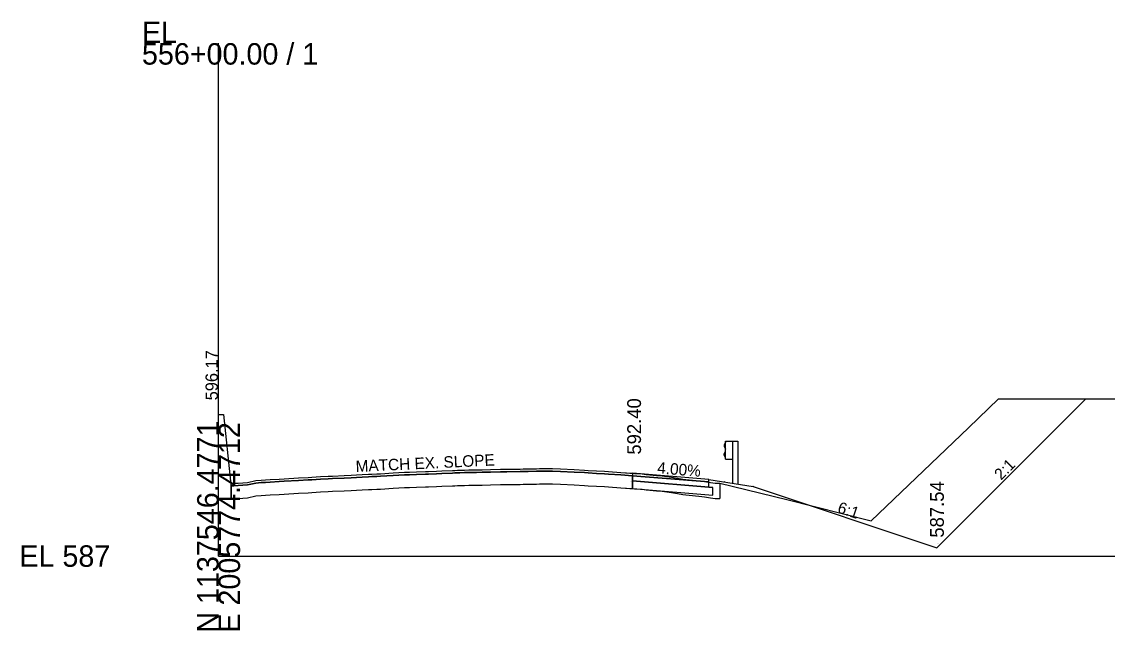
# Model space of a CAD drawing. Extents: x -201 to 2007062, y -213 to 1139737.
# Drawn here: x -25.7 to 116, y 8990.3 to 9069.8 of the extents above; entities that cross this region are included whole.
import ezdxf

# ---------------------------------------------------------------- set-up
doc = ezdxf.new("R2010")
doc.units = 0
for name, color, linetype in [('Default', 7, 'Continuous'), ('RD_GPK_XS_Cell', 7, 'Continuous'), ('RD_Sketch1', 7, 'Continuous'), ('RD_XS_Base', 7, 'Continuous'), ('RD_XS_ExGround', 7, 'Continuous'), ('RD_XS_ExPaveRet', 7, 'Continuous'), ('RD_XS_GR', 7, 'Continuous'), ('RD_XS_PaveOvlay', 7, 'Continuous'), ('RD_XS_PaveShd', 7, 'Continuous'), ('RD_XS_TieSlope', 7, 'Continuous'), ('RD_XS_TX_Ditch', 7, 'Continuous'), ('RD_XS_TX_Elev_EX', 7, 'Continuous'), ('RD_XS_TX_Elev_PR', 7, 'Continuous'), ('RD_XS_TX_Slope', 7, 'Continuous')]:
    doc.layers.add(name, color=color, linetype=linetype)

msp = doc.modelspace()

# ---------------------------------------------------------------- linework, layer by layer
at = {"layer": 'RD_GPK_XS_Cell'}
for q in [(0, 9066.96), (250, 9000)]:
    msp.add_line((0, 9000), q, dxfattribs=at)
at = {"layer": 'RD_XS_Base'}
for points in [[(64, 9009.67), (54, 9010.47)], [(54, 9010.47), (54, 9009.81)], [(64.5, 9008.97), (54, 9009.81)], [(54, 9009.81), (54, 9008.81)], [(54, 9009.81), (64.5, 9008.97)], [(64, 9009.01), (64, 9009.67)], [(54, 9008.81), (64.5, 9007.97)], [(64.5, 9007.97), (64.5, 9008.97)]]:
    msp.add_lwpolyline(points, dxfattribs=at)
at = {"layer": 'RD_XS_ExGround'}
msp.add_lwpolyline([(0, 9018.33), (0.02, 9018.49), (0.62, 9018.48), (1.54, 9009.76), (1.64, 9009.48), (1.99, 9009.5), (2.56, 9009.53), (3.79, 9009.61), (4.87, 9009.86), (5.55, 9009.92), (6.14, 9009.95), (6.74, 9009.99), (7.92, 9010.05), (8.58, 9010.09), (10.43, 9010.2), (11.71, 9010.27), (12.17, 9010.3), (13.28, 9010.37), (14.29, 9010.43), (14.85, 9010.45), (16.41, 9010.52), (17.31, 9010.56), (17.98, 9010.6), (18.72, 9010.66), (19.55, 9010.69), (20.02, 9010.71), (20.65, 9010.73), (21.12, 9010.75), (22.78, 9010.86), (24.25, 9010.93), (24.9, 9010.96), (25.82, 9010.99), (27.02, 9011.03), (27.38, 9011.04), (28.42, 9011.09), (29.14, 9011.12), (30.52, 9011.17), (30.83, 9011.18), (31.18, 9011.2), (31.49, 9011.21), (32.08, 9011.22), (32.64, 9011.24), (33.65, 9011.24), (34.41, 9011.26), (35.5, 9011.29), (36.79, 9011.33), (37.63, 9011.34), (39.38, 9011.36), (39.75, 9011.37), (40.41, 9011.38), (41.49, 9011.4), (41.87, 9011.41), (42.55, 9011.43), (42.98, 9011.43), (43.57, 9011.41), (44.62, 9011.39), (46.41, 9011.29), (47.76, 9011.22), (48.23, 9011.18), (49.32, 9011.11), (50.35, 9011.07), (50.89, 9011.04), (52.48, 9010.92), (54.27, 9010.78), (54.58, 9010.76), (55.3, 9010.72), (55.8, 9010.66), (56.72, 9010.56), (57.16, 9010.52), (57.87, 9010.46), (59.1, 9010.28), (59.9, 9010.16), (60.58, 9010.04), (60.96, 9010), (61.86, 9009.91), (63.08, 9009.78), (63.43, 9009.72), (64.18, 9009.59), (64.49, 9009.55), (64.79, 9009.5), (65.43, 9009.52), (74.18, 9007.39), (85.17, 9004.59), (97.87, 9016.76), (101.8, 9020.52), (113.57, 9020.53), (120.72, 9020.53)], dxfattribs=at)
at = {"layer": 'RD_XS_ExPaveRet'}
for p, q in [((1.64, 9007.48), (1.64, 9009.48)), ((1.64, 9009.15), (1.64, 9007.48)), ((27.38, 9009.04), (28.42, 9009.09)), ((27.38, 9009.04), (28.42, 9009.09)), ((28.42, 9009.09), (29.14, 9009.12)), ((28.42, 9009.09), (29.14, 9009.12)), ((29.14, 9009.12), (30.52, 9009.17)), ((29.14, 9009.12), (30.52, 9009.17)), ((30.52, 9009.17), (30.83, 9009.18)), ((30.52, 9009.17), (30.83, 9009.18)), ((30.83, 9009.18), (31.18, 9009.2)), ((30.83, 9009.18), (31.18, 9009.2)), ((31.18, 9009.2), (31.49, 9009.21)), ((31.18, 9009.2), (31.49, 9009.21)), ((31.49, 9009.21), (32.08, 9009.22)), ((31.49, 9009.21), (32.08, 9009.22)), ((32.08, 9009.22), (32.64, 9009.24)), ((32.08, 9009.22), (32.64, 9009.24)), ((32.64, 9009.24), (33.65, 9009.24)), ((32.64, 9009.24), (33.65, 9009.24)), ((33.65, 9009.24), (34.41, 9009.26)), ((33.65, 9009.24), (34.41, 9009.26)), ((34.41, 9009.26), (35.5, 9009.29)), ((34.41, 9009.26), (35.5, 9009.29)), ((35.5, 9009.29), (36.79, 9009.33)), ((35.5, 9009.29), (36.79, 9009.33)), ((36.79, 9009.33), (37.63, 9009.34)), ((36.79, 9009.33), (37.63, 9009.34)), ((37.63, 9009.34), (39.38, 9009.36)), ((37.63, 9009.34), (39.38, 9009.36)), ((39.38, 9009.36), (39.75, 9009.37)), ((39.38, 9009.36), (39.75, 9009.37)), ((39.75, 9009.37), (40.41, 9009.38)), ((39.75, 9009.37), (40.41, 9009.38)), ((40.41, 9009.38), (41.49, 9009.4)), ((40.41, 9009.38), (41.49, 9009.4)), ((41.49, 9009.4), (41.87, 9009.41)), ((41.49, 9009.4), (41.87, 9009.41)), ((41.87, 9009.41), (42.55, 9009.43)), ((41.87, 9009.41), (42.55, 9009.43)), ((42.55, 9009.43), (42.98, 9009.43)), ((42.55, 9009.43), (42.98, 9009.43)), ((42.98, 9009.43), (43.57, 9009.41)), ((42.98, 9009.43), (43.57, 9009.41)), ((43.57, 9009.41), (44.62, 9009.39)), ((43.57, 9009.41), (44.62, 9009.39)), ((44.62, 9009.39), (46.41, 9009.29)), ((44.62, 9009.39), (46.41, 9009.29)), ((46.41, 9009.29), (47.76, 9009.22)), ((46.41, 9009.29), (47.76, 9009.22)), ((47.76, 9009.22), (48.23, 9009.18)), ((47.76, 9009.22), (48.23, 9009.18)), ((48.23, 9009.18), (49.32, 9009.11)), ((48.23, 9009.18), (49.32, 9009.11)), ((49.32, 9009.11), (50.35, 9009.07)), ((49.32, 9009.11), (50.35, 9009.07)), ((50.35, 9009.07), (50.89, 9009.04)), ((50.35, 9009.07), (50.89, 9009.04)), ((54, 9009.81), (54, 9010.47)), ((54, 9008.81), (54, 9009.81)), ((65.43, 9009.52), (65.43, 9007.52)), ((3.79, 9007.61), (4.87, 9007.86)), ((3.79, 9007.61), (4.87, 9007.86)), ((4.87, 9007.86), (5.55, 9007.92)), ((4.87, 9007.86), (5.55, 9007.92)), ((5.55, 9007.92), (6.14, 9007.95)), ((5.55, 9007.92), (6.14, 9007.95)), ((6.14, 9007.95), (6.74, 9007.99)), ((6.14, 9007.95), (6.74, 9007.99)), ((6.74, 9007.99), (7.92, 9008.05)), ((6.74, 9007.99), (7.92, 9008.05)), ((7.92, 9008.05), (8.58, 9008.09)), ((7.92, 9008.05), (8.58, 9008.09)), ((8.58, 9008.09), (10.43, 9008.2)), ((8.58, 9008.09), (10.43, 9008.2)), ((10.43, 9008.2), (11.71, 9008.27)), ((10.43, 9008.2), (11.71, 9008.27)), ((11.71, 9008.27), (12.17, 9008.3)), ((11.71, 9008.27), (12.17, 9008.3)), ((12.17, 9008.3), (13.28, 9008.37)), ((12.17, 9008.3), (13.28, 9008.37)), ((13.28, 9008.37), (14.29, 9008.43)), ((13.28, 9008.37), (14.29, 9008.43)), ((14.29, 9008.43), (14.85, 9008.45)), ((14.29, 9008.43), (14.85, 9008.45)), ((14.85, 9008.45), (16.41, 9008.52)), ((14.85, 9008.45), (16.41, 9008.52)), ((16.41, 9008.52), (17.31, 9008.56)), ((16.41, 9008.52), (17.31, 9008.56)), ((17.31, 9008.56), (17.98, 9008.6)), ((17.31, 9008.56), (17.98, 9008.6)), ((17.98, 9008.6), (18.72, 9008.66)), ((17.98, 9008.6), (18.72, 9008.66)), ((18.72, 9008.66), (19.55, 9008.69)), ((18.72, 9008.66), (19.55, 9008.69)), ((19.55, 9008.69), (20.02, 9008.71)), ((19.55, 9008.69), (20.02, 9008.71)), ((20.02, 9008.71), (20.65, 9008.73)), ((20.02, 9008.71), (20.65, 9008.73)), ((20.65, 9008.73), (21.12, 9008.75)), ((20.65, 9008.73), (21.12, 9008.75)), ((21.12, 9008.75), (22.78, 9008.86)), ((21.12, 9008.75), (22.78, 9008.86)), ((22.78, 9008.86), (24.25, 9008.93)), ((22.78, 9008.86), (24.25, 9008.93)), ((24.25, 9008.93), (24.9, 9008.96)), ((24.25, 9008.93), (24.9, 9008.96)), ((24.9, 9008.96), (25.82, 9008.99)), ((24.9, 9008.96), (25.82, 9008.99)), ((25.82, 9008.99), (27.02, 9009.03)), ((25.82, 9008.99), (27.02, 9009.03)), ((27.02, 9009.03), (27.38, 9009.04)), ((27.02, 9009.03), (27.38, 9009.04)), ((50.89, 9009.04), (52.48, 9008.92)), ((50.89, 9009.04), (52.48, 9008.92)), ((52.48, 9008.92), (54.27, 9008.78)), ((52.48, 9008.92), (54, 9008.8)), ((54, 9008.81), (54, 9008.8)), ((54, 9008.8), (54, 9008.81)), ((54.27, 9008.78), (54.58, 9008.76)), ((54.58, 9008.76), (55.3, 9008.72)), ((55.3, 9008.72), (55.8, 9008.66)), ((55.8, 9008.66), (56.72, 9008.56)), ((56.72, 9008.56), (57.16, 9008.52)), ((57.16, 9008.52), (57.87, 9008.46)), ((57.87, 9008.46), (59.1, 9008.28)), ((59.1, 9008.28), (59.9, 9008.16)), ((59.9, 9008.16), (60.58, 9008.04)), ((60.58, 9008.04), (60.96, 9008)), ((60.96, 9008), (61.86, 9007.91)), ((61.86, 9007.91), (63.08, 9007.78)), ((63.08, 9007.78), (63.43, 9007.72)), ((63.43, 9007.72), (64.18, 9007.59)), ((1.64, 9007.48), (1.99, 9007.5)), ((1.64, 9007.48), (1.99, 9007.5)), ((1.99, 9007.5), (2.56, 9007.53)), ((1.99, 9007.5), (2.56, 9007.53)), ((2.56, 9007.53), (3.79, 9007.61)), ((2.56, 9007.53), (3.79, 9007.61)), ((64.18, 9007.59), (64.49, 9007.55)), ((64.49, 9007.55), (64.79, 9007.5)), ((64.79, 9007.5), (65.43, 9007.52)), ((65.43, 9007.52), (65.43, 9007.52))]:
    msp.add_line(p, q, dxfattribs=at)
for points in [[(54, 9010.47), (52.48, 9010.59), (50.89, 9010.71), (50.35, 9010.73), (49.32, 9010.78), (48.23, 9010.85), (47.76, 9010.89), (46.41, 9010.96), (44.62, 9011.05), (43.57, 9011.08), (42.98, 9011.1), (42.55, 9011.09), (41.87, 9011.08), (41.49, 9011.07), (40.41, 9011.05), (39.75, 9011.03), (39.38, 9011.03), (37.63, 9011), (36.79, 9011), (35.5, 9010.96), (34.41, 9010.93), (33.65, 9010.9), (32.64, 9010.9), (32.08, 9010.89), (31.49, 9010.87), (31.18, 9010.87), (30.83, 9010.85), (30.52, 9010.84), (29.14, 9010.78), (28.42, 9010.75), (27.38, 9010.71), (27.02, 9010.7), (25.82, 9010.66), (24.9, 9010.62), (24.25, 9010.59), (22.78, 9010.52), (21.12, 9010.42), (20.65, 9010.4), (20.02, 9010.37), (19.55, 9010.36), (18.72, 9010.32), (17.98, 9010.27), (17.31, 9010.22), (16.41, 9010.19), (14.85, 9010.12), (14.29, 9010.09), (13.28, 9010.04), (12.17, 9009.97), (11.71, 9009.94), (10.43, 9009.87), (8.58, 9009.76), (7.92, 9009.72), (6.74, 9009.66), (6.14, 9009.62), (5.55, 9009.59), (4.87, 9009.53), (3.79, 9009.28), (2.56, 9009.19), (1.99, 9009.17), (1.64, 9009.15)], [(1.64, 9009.15), (1.64, 9009.15)]]:
    msp.add_lwpolyline(points, dxfattribs=at)
at = {"layer": 'RD_XS_GR'}
for p, q in [((66.17, 9014.86), (66, 9014.46)), ((66.17, 9012.67), (66.17, 9015)), ((66.17, 9015), (67.08, 9015)), ((67.08, 9015), (67.08, 9009.51)), ((67.08, 9015), (67.75, 9015)), ((67.75, 9015), (67.75, 9009.4)), ((66, 9014.46), (66, 9014.36)), ((66, 9014.36), (66.17, 9013.96)), ((66, 9013.31), (66.17, 9013.71)), ((66, 9013.21), (66, 9013.31)), ((66.17, 9012.81), (66, 9013.21)), ((66.17, 9012.67), (67.08, 9012.67))]:
    msp.add_line(p, q, dxfattribs=at)
for centre, major_axis in [((66, 9009.69), (0, -0.02)), ((69.75, 9009.09), (0, -0.0204))]:
    msp.add_ellipse(centre, major_axis=major_axis, ratio=0.5, dxfattribs=at)
at = {"layer": 'RD_XS_PaveOvlay'}
for points in [[(1.64, 9009.48), (1.99, 9009.5), (2.56, 9009.53), (3.79, 9009.61), (4.87, 9009.86), (5.55, 9009.92), (6.14, 9009.95), (6.74, 9009.99), (7.92, 9010.05), (8.58, 9010.09), (10.43, 9010.2), (11.71, 9010.27), (12.17, 9010.3), (13.28, 9010.37), (14.29, 9010.43), (14.85, 9010.45), (16.41, 9010.52), (17.31, 9010.56), (17.98, 9010.6), (18.72, 9010.66), (19.55, 9010.69), (20.02, 9010.71), (20.65, 9010.73), (21.12, 9010.75), (22.78, 9010.86), (24.25, 9010.93), (24.9, 9010.96), (25.82, 9010.99), (27.02, 9011.03), (27.38, 9011.04), (28.42, 9011.09), (29.14, 9011.12), (30.52, 9011.17), (30.83, 9011.18), (31.18, 9011.2), (31.49, 9011.21), (32.08, 9011.22), (32.64, 9011.24), (33.65, 9011.24), (34.41, 9011.26), (35.5, 9011.29), (36.79, 9011.33), (37.63, 9011.34), (39.38, 9011.36), (39.75, 9011.37), (40.41, 9011.38), (41.49, 9011.4), (41.87, 9011.41), (42.55, 9011.43), (42.98, 9011.43), (43.57, 9011.41), (44.62, 9011.39), (46.41, 9011.29), (47.76, 9011.22), (48.23, 9011.18), (49.32, 9011.11), (50.35, 9011.07), (50.89, 9011.04), (52.48, 9010.92), (54, 9010.8)], [(1.64, 9009.15), (1.99, 9009.17), (2.56, 9009.19), (3.79, 9009.28), (4.87, 9009.53), (5.55, 9009.59), (6.14, 9009.62), (6.74, 9009.66), (7.92, 9009.72), (8.58, 9009.76), (10.43, 9009.87), (11.71, 9009.94), (12.17, 9009.97), (13.28, 9010.04), (14.29, 9010.09), (14.85, 9010.12), (16.41, 9010.19), (17.31, 9010.22), (17.98, 9010.27), (18.72, 9010.32), (19.55, 9010.36), (20.02, 9010.37), (20.65, 9010.4), (21.12, 9010.42), (22.78, 9010.52), (24.25, 9010.59), (24.9, 9010.62), (25.82, 9010.66), (27.02, 9010.7), (27.38, 9010.71), (28.42, 9010.75), (29.14, 9010.78), (30.52, 9010.84), (30.83, 9010.85), (31.18, 9010.87), (31.49, 9010.87), (32.08, 9010.89), (32.64, 9010.9), (33.65, 9010.9), (34.41, 9010.93), (35.5, 9010.96), (36.79, 9011), (37.63, 9011), (39.38, 9011.03), (39.75, 9011.03), (40.41, 9011.05), (41.49, 9011.07), (41.87, 9011.08), (42.55, 9011.09), (42.98, 9011.1), (43.57, 9011.08), (44.62, 9011.05), (46.41, 9010.96), (47.76, 9010.89), (48.23, 9010.85), (49.32, 9010.78), (50.35, 9010.73), (50.89, 9010.71), (52.48, 9010.59), (54, 9010.47)]]:
    msp.add_lwpolyline(points, dxfattribs=at)
at = {"layer": 'RD_XS_PaveShd'}
for points in [[(64, 9010.01), (54, 9010.81)], [(54, 9010.81), (54, 9010.47)], [(54, 9010.47), (64, 9009.67)], [(64, 9009.67), (64, 9010.01)]]:
    msp.add_lwpolyline(points, dxfattribs=at)
at = {"layer": 'RD_XS_TieSlope'}
msp.add_line((64, 9010.01), (69.75, 9009.09), dxfattribs=at)
msp.add_lwpolyline([(69.75, 9009.09), (93.75, 9001.09), (113.2, 9020.53)], dxfattribs=at)

# ---------------------------------------------------------------- texts
at = {"layer": 'Default'}
msp.add_text('-', height=0.0001, dxfattribs=at).set_placement((0, 9000))
at = {"layer": 'RD_GPK_XS_Cell'}
for s, p in [('EL', (-10, 9066.96)), ('556+00.00 / 1', (-10, 9064.16)), ('EL 587', (-26, 8998.6))]:
    msp.add_text(s, height=2.8, dxfattribs=at).set_placement(p)
for s, p in [('N 1137546.4771', (0, 8990)), ('E 2005774.4712', (2.8, 8990))]:
    msp.add_text(s, height=2.8, rotation=90, dxfattribs=at).set_placement(p)
at = {"layer": 'RD_Sketch1'}
for s, p in [('Exterior Boundary', (112.29, 9020.48)), ('LOC_C_R', (112.52, 9020.48)), ('Exterior Boundary', (53.44, 9010.76)), ('EP_X_R', (53.73, 9010.76)), ('EP_X2', (53.79, 9009.76)), ('EP_X1', (53.8, 9010.42)), ('EP_X3', (53.79, 9008.76)), ('Cut_Ditch_R', (93.6, 9001.64))]:
    msp.add_text(s, height=0.05, dxfattribs=at).set_placement(p)
at = {"layer": 'RD_XS_TX_Ditch'}
msp.add_text('587.54', height=1.8, rotation=90, dxfattribs=at).set_placement((94.65, 9002.4))
at = {"layer": 'RD_XS_TX_Elev_EX'}
msp.add_text('596.17', height=1.6, rotation=90, dxfattribs=at).set_placement((-0.1, 9020.33))
at = {"layer": 'RD_XS_TX_Elev_PR'}
msp.add_text('592.40', height=1.8, rotation=90, dxfattribs=at).set_placement((55.13, 9013.24))
at = {"layer": 'RD_XS_TX_Slope'}
for s, rotation, p in [('MATCH EX. SLOPE', 2.7318, (17.92, 9010.96)), ('4.00%', 355.4261, (57.2, 9010.8)), ('2:1', 45, (102.13, 9009.82)), ('6:1', 341.5651, (80.66, 9005.71))]:
    msp.add_text(s, height=1.5, rotation=rotation, dxfattribs=at).set_placement(p)

doc.saveas('drawing.dxf')
